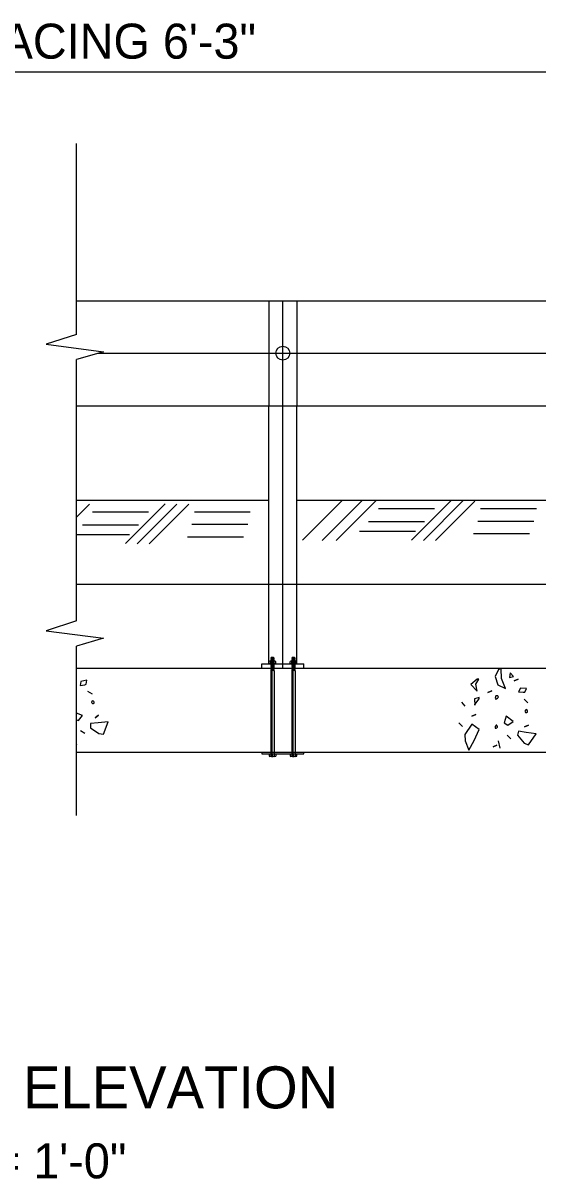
# Model space of a CAD drawing. Extents: x 0 to 90.7, y 0 to 62.8.
# Drawn here: x 26.31 to 32.44, y 29.79 to 43.55 of the extents above; entities that cross this region are included whole.
import ezdxf

# ---------------------------------------------------------------- set-up
doc = ezdxf.new("R2010")
doc.units = 0
for name, color, linetype in [('BRDG_ANNO_General-Notes', 7, 'Continuous'), ('BRDG_BASE_Ground-Lines', 7, 'Continuous'), ('BRDG_BASE_Hidden-Line', 7, 'Continuous'), ('BRDG_BASE_Obj-Line', 7, 'Continuous'), ('BRDG_BASE_Pattern', 7, 'Continuous')]:
    doc.layers.add(name, color=color, linetype=linetype)

msp = doc.modelspace()

# ---------------------------------------------------------------- linework, layer by layer
at = {"layer": 'BRDG_ANNO_General-Notes'}
for p, q in [((16.903, 42.967), (35.653, 42.967)), ((26.946, 34.957), (26.947, 34.953))]:
    msp.add_line(p, q, dxfattribs=at)
msp.add_lwpolyline([(26.946, 35.801), (26.947, 35.803), (26.946, 35.801)], dxfattribs=at)
at = {"layer": 'BRDG_BASE_Ground-Lines'}
for p, q in [((30.111, 37.862), (29.639, 37.391)), ((30.343, 37.857), (29.872, 37.386)), ((30.509, 37.86), (30.037, 37.388)), ((31.408, 37.862), (30.937, 37.391)), ((31.548, 37.857), (31.077, 37.386)), ((31.69, 37.856), (31.219, 37.385)), ((27.103, 37.82), (26.946, 37.663)), ((27.137, 37.727), (27.804, 37.727)), ((28.002, 37.823), (27.531, 37.352)), ((28.142, 37.818), (27.671, 37.347)), ((28.284, 37.817), (27.813, 37.346)), ((28.35, 37.727), (29.016, 37.727)), ((30.543, 37.766), (31.21, 37.766)), ((31.755, 37.766), (32.422, 37.766)), ((27.017, 37.574), (27.684, 37.574)), ((28.319, 37.579), (28.986, 37.579)), ((30.423, 37.613), (31.09, 37.613)), ((31.725, 37.618), (32.392, 37.618)), ((26.946, 37.456), (27.578, 37.456)), ((28.269, 37.429), (28.936, 37.429)), ((30.318, 37.496), (30.984, 37.496)), ((31.675, 37.468), (32.342, 37.468))]:
    msp.add_line(p, q, dxfattribs=at)
at = {"layer": 'BRDG_BASE_Hidden-Line'}
for p, q in [((29.279, 35.968), (29.279, 35.917)), ((29.279, 35.948), (29.279, 35.918)), ((29.529, 35.968), (29.529, 35.917)), ((29.529, 35.948), (29.529, 35.918)), ((29.279, 34.814), (29.279, 34.844)), ((29.529, 34.814), (29.529, 34.844))]:
    msp.add_line(p, q, dxfattribs=at)
at = {"layer": 'BRDG_BASE_Obj-Line'}
for p, q in [((26.945, 39.84), (26.945, 42.113)), ((26.946, 40.241), (48.236, 40.241)), ((29.237, 40.241), (29.237, 38.991)), ((29.403, 35.866), (29.403, 40.241)), ((29.57, 40.241), (29.57, 38.991)), ((26.945, 39.84), (26.585, 39.723)), ((26.585, 39.723), (27.267, 39.633)), ((27.267, 39.633), (26.945, 39.541)), ((26.945, 36.429), (26.945, 39.541)), ((27.195, 39.616), (48.236, 39.616)), ((29.403, 39.616), (29.403, 39.616)), ((26.946, 38.991), (48.236, 38.991)), ((29.237, 35.918), (29.237, 38.991)), ((29.57, 35.918), (29.57, 38.991)), ((26.946, 37.866), (29.237, 37.866)), ((29.57, 37.866), (35.487, 37.866)), ((26.946, 36.866), (38.653, 36.866)), ((26.945, 36.429), (26.585, 36.312)), ((26.585, 36.312), (27.267, 36.222)), ((27.267, 36.222), (26.945, 36.13)), ((26.945, 34.113), (26.945, 36.13)), ((29.153, 35.918), (29.653, 35.918)), ((29.153, 35.866), (29.153, 35.918)), ((29.239, 35.92), (29.239, 35.945)), ((29.317, 35.918), (29.241, 35.918)), ((29.309, 35.948), (29.249, 35.948)), ((29.264, 35.994), (29.259, 35.991)), ((29.294, 35.994), (29.259, 35.991)), ((29.264, 35.987), (29.259, 35.991)), ((29.264, 35.987), (29.259, 35.984)), ((29.299, 35.987), (29.259, 35.984)), ((29.264, 35.981), (29.259, 35.984)), ((29.264, 35.981), (29.259, 35.977)), ((29.299, 35.981), (29.259, 35.977)), ((29.264, 35.974), (29.259, 35.977)), ((29.264, 35.974), (29.259, 35.971)), ((29.299, 35.974), (29.259, 35.971)), ((29.264, 35.968), (29.259, 35.971)), ((29.264, 35.968), (29.259, 35.964)), ((29.299, 35.968), (29.259, 35.964)), ((29.264, 35.961), (29.259, 35.964)), ((29.264, 35.961), (29.259, 35.958)), ((29.299, 35.961), (29.259, 35.958)), ((29.264, 35.954), (29.259, 35.958)), ((29.264, 35.954), (29.259, 35.951)), ((29.299, 35.954), (29.259, 35.951)), ((29.264, 35.948), (29.259, 35.951)), ((29.264, 35.948), (29.259, 35.944)), ((29.299, 35.948), (29.259, 35.944)), ((29.259, 35.918), (29.259, 35.945)), ((29.264, 35.941), (29.259, 35.944)), ((29.264, 35.941), (29.259, 35.938)), ((29.299, 35.941), (29.259, 35.938)), ((29.264, 35.935), (29.259, 35.938)), ((29.264, 35.935), (29.259, 35.931)), ((29.299, 35.935), (29.259, 35.931)), ((29.264, 35.928), (29.259, 35.931)), ((29.264, 35.928), (29.259, 35.925)), ((29.299, 35.928), (29.259, 35.925)), ((29.264, 35.921), (29.259, 35.925)), ((29.264, 35.921), (29.259, 35.918)), ((29.299, 35.921), (29.259, 35.918)), ((29.264, 35.915), (29.259, 35.918)), ((29.264, 35.915), (29.259, 35.911)), ((29.299, 35.915), (29.259, 35.911)), ((29.264, 35.908), (29.259, 35.911)), ((29.294, 35.994), (29.264, 35.994)), ((29.294, 35.991), (29.264, 35.987)), ((29.294, 35.984), (29.264, 35.981)), ((29.294, 35.977), (29.264, 35.974)), ((29.294, 35.971), (29.264, 35.968)), ((29.294, 35.964), (29.264, 35.961)), ((29.294, 35.958), (29.264, 35.954)), ((29.294, 35.951), (29.264, 35.948)), ((29.294, 35.944), (29.264, 35.941)), ((29.294, 35.938), (29.264, 35.935)), ((29.294, 35.931), (29.264, 35.928)), ((29.294, 35.925), (29.264, 35.921)), ((29.294, 35.918), (29.264, 35.915)), ((29.294, 35.911), (29.264, 35.908)), ((29.278, 34.845), (29.278, 35.918)), ((29.294, 35.994), (29.296, 35.992)), ((29.294, 35.991), (29.296, 35.992)), ((29.294, 35.991), (29.299, 35.987)), ((29.294, 35.984), (29.299, 35.987)), ((29.294, 35.984), (29.299, 35.981)), ((29.294, 35.977), (29.299, 35.981)), ((29.294, 35.977), (29.299, 35.974)), ((29.294, 35.971), (29.299, 35.974)), ((29.294, 35.971), (29.299, 35.968)), ((29.294, 35.964), (29.299, 35.968)), ((29.294, 35.964), (29.299, 35.961)), ((29.294, 35.958), (29.299, 35.961)), ((29.294, 35.958), (29.299, 35.954)), ((29.294, 35.951), (29.299, 35.954)), ((29.294, 35.951), (29.299, 35.948)), ((29.294, 35.944), (29.299, 35.948)), ((29.294, 35.944), (29.299, 35.941)), ((29.294, 35.938), (29.299, 35.941)), ((29.294, 35.938), (29.299, 35.935)), ((29.294, 35.931), (29.299, 35.935)), ((29.294, 35.931), (29.299, 35.928)), ((29.294, 35.925), (29.299, 35.928)), ((29.294, 35.925), (29.299, 35.921)), ((29.294, 35.918), (29.299, 35.921)), ((29.294, 35.918), (29.299, 35.915)), ((29.294, 35.911), (29.299, 35.915)), ((29.294, 35.911), (29.299, 35.908)), ((29.299, 35.918), (29.299, 35.945)), ((29.319, 35.92), (29.319, 35.945)), ((29.489, 35.92), (29.489, 35.945)), ((29.567, 35.918), (29.491, 35.918)), ((29.559, 35.948), (29.499, 35.948)), ((29.514, 35.994), (29.509, 35.991)), ((29.544, 35.994), (29.509, 35.991)), ((29.514, 35.987), (29.509, 35.991)), ((29.514, 35.987), (29.509, 35.984)), ((29.549, 35.987), (29.509, 35.984)), ((29.514, 35.981), (29.509, 35.984)), ((29.514, 35.981), (29.509, 35.977)), ((29.549, 35.981), (29.509, 35.977)), ((29.514, 35.974), (29.509, 35.977)), ((29.514, 35.974), (29.509, 35.971)), ((29.549, 35.974), (29.509, 35.971)), ((29.514, 35.968), (29.509, 35.971)), ((29.514, 35.968), (29.509, 35.964)), ((29.549, 35.968), (29.509, 35.964)), ((29.514, 35.961), (29.509, 35.964)), ((29.514, 35.961), (29.509, 35.958)), ((29.549, 35.961), (29.509, 35.958)), ((29.514, 35.954), (29.509, 35.958)), ((29.514, 35.954), (29.509, 35.951)), ((29.549, 35.954), (29.509, 35.951)), ((29.514, 35.948), (29.509, 35.951)), ((29.514, 35.948), (29.509, 35.944)), ((29.549, 35.948), (29.509, 35.944)), ((29.509, 35.918), (29.509, 35.945)), ((29.514, 35.941), (29.509, 35.944)), ((29.514, 35.941), (29.509, 35.938)), ((29.549, 35.941), (29.509, 35.938)), ((29.514, 35.935), (29.509, 35.938)), ((29.514, 35.935), (29.509, 35.931)), ((29.549, 35.935), (29.509, 35.931)), ((29.514, 35.928), (29.509, 35.931)), ((29.514, 35.928), (29.509, 35.925)), ((29.549, 35.928), (29.509, 35.925)), ((29.514, 35.921), (29.509, 35.925)), ((29.514, 35.921), (29.509, 35.918)), ((29.549, 35.921), (29.509, 35.918)), ((29.514, 35.915), (29.509, 35.918)), ((29.514, 35.915), (29.509, 35.911)), ((29.549, 35.915), (29.509, 35.911)), ((29.514, 35.908), (29.509, 35.911)), ((29.544, 35.994), (29.514, 35.994)), ((29.544, 35.991), (29.514, 35.987)), ((29.544, 35.984), (29.514, 35.981)), ((29.544, 35.977), (29.514, 35.974)), ((29.544, 35.971), (29.514, 35.968)), ((29.544, 35.964), (29.514, 35.961)), ((29.544, 35.958), (29.514, 35.954)), ((29.544, 35.951), (29.514, 35.948)), ((29.544, 35.944), (29.514, 35.941)), ((29.544, 35.938), (29.514, 35.935)), ((29.544, 35.931), (29.514, 35.928)), ((29.544, 35.925), (29.514, 35.921)), ((29.544, 35.918), (29.514, 35.915)), ((29.544, 35.911), (29.514, 35.908)), ((29.528, 34.845), (29.528, 35.918)), ((29.544, 35.994), (29.546, 35.992)), ((29.544, 35.991), (29.546, 35.992)), ((29.544, 35.991), (29.549, 35.987)), ((29.544, 35.984), (29.549, 35.987)), ((29.544, 35.984), (29.549, 35.981)), ((29.544, 35.977), (29.549, 35.981)), ((29.544, 35.977), (29.549, 35.974)), ((29.544, 35.971), (29.549, 35.974)), ((29.544, 35.971), (29.549, 35.968)), ((29.544, 35.964), (29.549, 35.968)), ((29.544, 35.964), (29.549, 35.961)), ((29.544, 35.958), (29.549, 35.961)), ((29.544, 35.958), (29.549, 35.954)), ((29.544, 35.951), (29.549, 35.954)), ((29.544, 35.951), (29.549, 35.948)), ((29.544, 35.944), (29.549, 35.948)), ((29.544, 35.944), (29.549, 35.941)), ((29.544, 35.938), (29.549, 35.941)), ((29.544, 35.938), (29.549, 35.935)), ((29.544, 35.931), (29.549, 35.935)), ((29.544, 35.931), (29.549, 35.928)), ((29.544, 35.925), (29.549, 35.928)), ((29.544, 35.925), (29.549, 35.921)), ((29.544, 35.918), (29.549, 35.921)), ((29.544, 35.918), (29.549, 35.915)), ((29.544, 35.911), (29.549, 35.915)), ((29.544, 35.911), (29.549, 35.908)), ((29.549, 35.918), (29.549, 35.945)), ((29.568, 35.92), (29.568, 35.945)), ((29.653, 35.866), (29.653, 35.918)), ((26.946, 35.866), (38.653, 35.866)), ((29.264, 35.908), (29.259, 35.905)), ((29.299, 35.908), (29.259, 35.905)), ((29.264, 35.902), (29.259, 35.905)), ((29.264, 35.902), (29.259, 35.898)), ((29.299, 35.902), (29.259, 35.898)), ((29.264, 35.895), (29.259, 35.898)), ((29.264, 35.895), (29.259, 35.892)), ((29.299, 35.895), (29.259, 35.892)), ((29.264, 35.888), (29.259, 35.892)), ((29.264, 35.888), (29.259, 35.885)), ((29.299, 35.888), (29.259, 35.885)), ((29.264, 35.882), (29.259, 35.885)), ((29.264, 35.882), (29.259, 35.878)), ((29.299, 35.882), (29.259, 35.878)), ((29.264, 35.875), (29.259, 35.878)), ((29.264, 35.875), (29.259, 35.872)), ((29.299, 35.875), (29.259, 35.872)), ((29.264, 35.869), (29.259, 35.872)), ((29.264, 35.869), (29.259, 35.865)), ((29.299, 35.869), (29.259, 35.865)), ((29.264, 35.862), (29.259, 35.865)), ((29.264, 35.862), (29.259, 35.859)), ((29.299, 35.862), (29.259, 35.859)), ((29.264, 35.855), (29.259, 35.859)), ((29.264, 35.855), (29.259, 35.852)), ((29.299, 35.855), (29.259, 35.852)), ((29.264, 35.849), (29.259, 35.852)), ((29.264, 35.849), (29.259, 35.845)), ((29.299, 35.849), (29.259, 35.845)), ((29.264, 35.842), (29.259, 35.845)), ((29.264, 35.842), (29.259, 35.839)), ((29.299, 35.842), (29.259, 35.839)), ((29.259, 35.839), (29.259, 34.844)), ((29.294, 35.905), (29.264, 35.902)), ((29.294, 35.898), (29.264, 35.895)), ((29.294, 35.892), (29.264, 35.888)), ((29.294, 35.885), (29.264, 35.882)), ((29.294, 35.878), (29.264, 35.875)), ((29.294, 35.872), (29.264, 35.869)), ((29.294, 35.865), (29.264, 35.862)), ((29.294, 35.859), (29.264, 35.855)), ((29.294, 35.852), (29.264, 35.849)), ((29.294, 35.845), (29.264, 35.842)), ((29.294, 35.839), (29.279, 35.837)), ((29.294, 35.905), (29.299, 35.908)), ((29.294, 35.905), (29.299, 35.902)), ((29.294, 35.898), (29.299, 35.902)), ((29.294, 35.898), (29.299, 35.895)), ((29.294, 35.892), (29.299, 35.895)), ((29.294, 35.892), (29.299, 35.888)), ((29.294, 35.885), (29.299, 35.888)), ((29.294, 35.885), (29.299, 35.882)), ((29.294, 35.878), (29.299, 35.882)), ((29.294, 35.878), (29.299, 35.875)), ((29.294, 35.872), (29.299, 35.875)), ((29.294, 35.872), (29.299, 35.869)), ((29.294, 35.865), (29.299, 35.869)), ((29.294, 35.865), (29.299, 35.862)), ((29.294, 35.859), (29.299, 35.862)), ((29.294, 35.859), (29.299, 35.855)), ((29.294, 35.852), (29.299, 35.855)), ((29.294, 35.852), (29.299, 35.849)), ((29.294, 35.845), (29.299, 35.849)), ((29.294, 35.845), (29.299, 35.842)), ((29.294, 35.839), (29.299, 35.842)), ((29.294, 35.839), (29.299, 35.836)), ((29.299, 35.836), (29.299, 34.844)), ((29.514, 35.908), (29.509, 35.905)), ((29.549, 35.908), (29.509, 35.905)), ((29.514, 35.902), (29.509, 35.905)), ((29.514, 35.902), (29.509, 35.898)), ((29.549, 35.902), (29.509, 35.898)), ((29.514, 35.895), (29.509, 35.898)), ((29.514, 35.895), (29.509, 35.892)), ((29.549, 35.895), (29.509, 35.892)), ((29.514, 35.888), (29.509, 35.892)), ((29.514, 35.888), (29.509, 35.885)), ((29.549, 35.888), (29.509, 35.885)), ((29.514, 35.882), (29.509, 35.885)), ((29.514, 35.882), (29.509, 35.878)), ((29.549, 35.882), (29.509, 35.878)), ((29.514, 35.875), (29.509, 35.878)), ((29.514, 35.875), (29.509, 35.872)), ((29.549, 35.875), (29.509, 35.872)), ((29.514, 35.869), (29.509, 35.872)), ((29.514, 35.869), (29.509, 35.865)), ((29.549, 35.869), (29.509, 35.865)), ((29.514, 35.862), (29.509, 35.865)), ((29.514, 35.862), (29.509, 35.859)), ((29.549, 35.862), (29.509, 35.859)), ((29.514, 35.855), (29.509, 35.859)), ((29.514, 35.855), (29.509, 35.852)), ((29.549, 35.855), (29.509, 35.852)), ((29.514, 35.849), (29.509, 35.852)), ((29.514, 35.849), (29.509, 35.845)), ((29.549, 35.849), (29.509, 35.845)), ((29.514, 35.842), (29.509, 35.845)), ((29.514, 35.842), (29.509, 35.839)), ((29.549, 35.842), (29.509, 35.839)), ((29.509, 35.839), (29.509, 34.844)), ((29.544, 35.905), (29.514, 35.902)), ((29.544, 35.898), (29.514, 35.895)), ((29.544, 35.892), (29.514, 35.888)), ((29.544, 35.885), (29.514, 35.882)), ((29.544, 35.878), (29.514, 35.875)), ((29.544, 35.872), (29.514, 35.869)), ((29.544, 35.865), (29.514, 35.862)), ((29.544, 35.859), (29.514, 35.855)), ((29.544, 35.852), (29.514, 35.849)), ((29.544, 35.845), (29.514, 35.842)), ((29.544, 35.839), (29.529, 35.837)), ((29.544, 35.905), (29.549, 35.908)), ((29.544, 35.905), (29.549, 35.902)), ((29.544, 35.898), (29.549, 35.902)), ((29.544, 35.898), (29.549, 35.895)), ((29.544, 35.892), (29.549, 35.895)), ((29.544, 35.892), (29.549, 35.888)), ((29.544, 35.885), (29.549, 35.888)), ((29.544, 35.885), (29.549, 35.882)), ((29.544, 35.878), (29.549, 35.882)), ((29.544, 35.878), (29.549, 35.875)), ((29.544, 35.872), (29.549, 35.875)), ((29.544, 35.872), (29.549, 35.869)), ((29.544, 35.865), (29.549, 35.869)), ((29.544, 35.865), (29.549, 35.862)), ((29.544, 35.859), (29.549, 35.862)), ((29.544, 35.859), (29.549, 35.855)), ((29.544, 35.852), (29.549, 35.855)), ((29.544, 35.852), (29.549, 35.849)), ((29.544, 35.845), (29.549, 35.849)), ((29.544, 35.845), (29.549, 35.842)), ((29.544, 35.839), (29.549, 35.842)), ((29.544, 35.839), (29.549, 35.836)), ((29.549, 35.836), (29.549, 34.844)), ((26.946, 34.866), (36.653, 34.866)), ((29.153, 34.866), (29.153, 34.845)), ((29.153, 34.845), (29.653, 34.845)), ((29.239, 34.842), (29.239, 34.818)), ((29.317, 34.844), (29.241, 34.844)), ((29.309, 34.814), (29.249, 34.814)), ((29.259, 34.844), (29.259, 34.818)), ((29.299, 34.844), (29.299, 34.818)), ((29.319, 34.842), (29.319, 34.818)), ((29.489, 34.842), (29.489, 34.818)), ((29.567, 34.844), (29.491, 34.844)), ((29.559, 34.814), (29.499, 34.814)), ((29.509, 34.844), (29.509, 34.818)), ((29.549, 34.844), (29.549, 34.818)), ((29.568, 34.842), (29.568, 34.818)), ((29.653, 34.845), (29.653, 34.866))]:
    msp.add_line(p, q, dxfattribs=at)
msp.add_circle((29.403, 39.616), 0.0833, dxfattribs=at)
for centre, radius, start, end in [((29.249, 35.933), 0.0157, 50.7833, 129.2167), ((29.241, 35.92), 0.00198, 180, 270), ((29.279, 35.893), 0.055, 68.9268, 111.0732), ((29.309, 35.933), 0.0157, 50.7833, 129.2167), ((29.317, 35.92), 0.00198, 270, 0), ((29.499, 35.933), 0.0157, 50.7833, 129.2167), ((29.491, 35.92), 0.00198, 180, 270), ((29.529, 35.893), 0.055, 68.9268, 111.0732), ((29.559, 35.933), 0.0157, 50.7833, 129.2167), ((29.566, 35.92), 0.00198, 270, 0), ((29.241, 34.842), 0.00198, 90, 180), ((29.249, 34.83), 0.0157, 230.7833, 309.2167), ((29.279, 34.869), 0.055, 248.9268, 291.0732), ((29.309, 34.83), 0.0157, 230.7833, 309.2167), ((29.317, 34.842), 0.00198, 0, 90), ((29.491, 34.842), 0.00198, 90, 180), ((29.499, 34.83), 0.0157, 230.7833, 309.2167), ((29.529, 34.869), 0.055, 248.9268, 291.0732), ((29.559, 34.83), 0.0157, 230.7833, 309.2167), ((29.566, 34.842), 0.00198, 0, 90)]:
    msp.add_arc(centre, radius, start, end, dxfattribs=at)
at = {"layer": 'BRDG_BASE_Pattern'}
for p, q in [((27.079, 35.592), (27.132, 35.559)), ((32.277, 35.497), (32.32, 35.452)), ((31.529, 35.462), (31.571, 35.416)), ((26.993, 35.126), (27.046, 35.093)), ((31.5, 35.217), (31.542, 35.171)), ((31.967, 35), (31.985, 34.914)), ((32.073, 35.069), (32.116, 35.024))]:
    msp.add_line(p, q, dxfattribs=at)
for points in [[(31.97, 35.849), (31.93, 35.768), (31.965, 35.669), (32.055, 35.624), (32.006, 35.745), (32.001, 35.858)], [(32.11, 35.81), (32.103, 35.755), (32.148, 35.767)], [(27, 35.707), (26.992, 35.66), (27.047, 35.668), (27.063, 35.676), (27.071, 35.723)], [(31.716, 35.736), (31.641, 35.67), (31.716, 35.593), (31.703, 35.674), (31.735, 35.736)], [(32.158, 35.715), (32.205, 35.735)], [(31.685, 35.501), (31.689, 35.426), (31.691, 35.433), (31.742, 35.501), (31.739, 35.519)], [(31.844, 35.575), (31.89, 35.595)], [(31.938, 35.539), (31.931, 35.511), (31.941, 35.498), (31.946, 35.501), (31.961, 35.509), (31.972, 35.522), (31.969, 35.531), (31.962, 35.537), (31.958, 35.538), (31.95, 35.538)], [(32.231, 35.629), (32.211, 35.586), (32.266, 35.579), (32.283, 35.582), (32.303, 35.626)], [(27.134, 35.478), (27.124, 35.456), (27.136, 35.445), (27.15, 35.445), (27.156, 35.451), (27.156, 35.463), (27.154, 35.468), (27.148, 35.474)], [(32.301, 35.373), (32.286, 35.355), (32.294, 35.34), (32.308, 35.337), (32.315, 35.341), (32.318, 35.352), (32.317, 35.358), (32.313, 35.366)], [(27.206, 35.214), (27.112, 35.206), (27.112, 35.158), (27.214, 35.088), (27.269, 35.08), (27.324, 35.229)], [(27.168, 35.276), (27.207, 35.307)], [(31.655, 35.294), (31.701, 35.314)], [(32.062, 35.294), (32.037, 35.214), (32.083, 35.189), (32.145, 35.231)], [(31.653, 35.199), (31.571, 35.075), (31.575, 35), (31.619, 34.891), (31.682, 35.004), (31.742, 35.135)], [(31.93, 35.173), (31.931, 35.152), (31.936, 35.151), (31.944, 35.151), (31.952, 35.155), (31.96, 35.165), (31.961, 35.177), (31.952, 35.181), (31.95, 35.186), (31.942, 35.188)], [(32.302, 35.099), (32.209, 35.116), (32.197, 35.07), (32.277, 34.975), (32.328, 34.953), (32.42, 35.083)], [(32.281, 35.169), (32.327, 35.189)], [(31.907, 34.929), (31.953, 34.949)]]:
    msp.add_lwpolyline(points, close=True, dxfattribs=at)
msp.add_lwpolyline([(26.946, 35.25), (26.971, 35.244), (27.02, 35.301), (26.946, 35.331)], dxfattribs=at)

# ---------------------------------------------------------------- texts
at = {"layer": 'BRDG_ANNO_General-Notes'}
for s, height, p in [('POST SPACING 6\'-3"', 0.41667, (23.641, 43.122)), ('GUARDRAIL ELEVATION', 0.5, (22.223, 30.626)), ('3/8" = 1\'-0"', 0.41667, (24.825, 29.793))]:
    msp.add_text(s, height=height, dxfattribs=at).set_placement(p)

doc.saveas('drawing.dxf')
